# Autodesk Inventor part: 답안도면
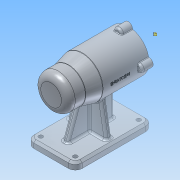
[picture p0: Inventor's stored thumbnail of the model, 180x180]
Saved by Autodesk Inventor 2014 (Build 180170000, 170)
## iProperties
Created: 2019-07
Part Number: 답안도면
Material: 알루미늄 6061
Document SubType Name: Modeling
Designer: net
Density: 2.71 g/cm^3
Appearance: 알루미늄 - 평지
Mass: 644.956 g
Surface Area: 654.406 cm^2
Volume: 237.991 cm^3
Author: net
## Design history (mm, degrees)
sketch "스케치1"
  geometry: L1 (-56, 0)-(56, 0); L2 (-56, 0)-(-50, 0); L3 (-50, 0)-(-50, 10.5); L4 (-50, 10.5)-(-47, 10.5); L5 (-47, 10.5)-(-47, 16); L6 (-47, 16)-(-43, 16); L7 (-43, 16)-(-43, 17.5); L8 (-43, 17.5)-(-25, 17.5); L9 (-25, 17.5)-(-25, 21); L10 (-25, 21)-(-13, 21); L11 (-13, 21)-(-13, 24); L12 (-13, 24)-(41, 24); L13 (41, 24)-(41, 21); L14 (41, 21)-(56, 21); L15 (56, 21)-(56, 30); L16 (56, 30)-(-11, 30); L17 (-31, 25)-(-56, 25); L18 (-56, 25)-(-56, 0); L19 (-31, 25)-(-11, 30); 2 further points
  constraints: 39 end point, 13 parallel, 3 perpendicular, 1 coincident, 1 collinear, 1 horizontal, 1 midpoint
  dimensions: "d0" = 112 distance of L1.start L1.end; "d1" = 42 diameter of L14 L1; "d2" = 60 diameter of L16 L1; "d3" = 50 diameter of L17 L1; "d4" = 48 diameter of L12 L1; "d5" = 42 diameter of L10 L1; "d6" = 35 diameter of L8 L1; "d7" = 32 diameter of L6 L1; "d9" = 21 diameter of L4 L1; "d10" = 15 distance of L13.end L14.end; "d11" = 112 distance between parallel lines of L15 L18; "d12" = 3 distance of L3.end L4.end; "d13" = 4 distance of L5.end L6.end; "d14" = 18 distance of L7.end L8.end; "d15" = 12 distance of L9.end L10.end; "d16" = 54 distance of L11.end L12.end; "d17" = 25 distance from line of L17.start L18; "d18" = 45 distance from line of L18 L16.end
revolve "회전1" sketch "스케치1" stored, may be unused: angle "d19" = 90 deg
fillet "모깎기1" dims "d20" = 10
fillet "모깎기2" dims "d21" = 3
fillet "모깎기3" dims "d22" = 3
fillet "모깎기4" dims "d23" = 0.3
fillet "모깎기5" dims "d24" = 3
node "작업 평면1"
sketch "스케치4"
  geometry: L1 (35, -56)-(-35, -56); L2 (-35, -56)-(-35, 56); L3 (-35, 56)-(35, 56); L4 (35, 56)-(35, -56); L5 (35, -56)-(-35, 56); L6 (-35, -56)-(35, 56); 1 further point
  constraints: 12 end point, 2 midpoint, 2 parallel, 1 horizontal, 1 perpendicular
  dimensions: "d26" = 70 distance of L2.end L3.end; "d27" = 112 distance of L1.end L2.end
extrude "돌출1" join sketch "스케치4" distance "d28" = 10; taper "d29" = 0 deg
fillet "모깎기6" dims "d30" = 10
sketch "스케치5"
  geometry: C1 r 3 at (-25, 46); C2 r 3 at (25, 46); C3 r 3 at (25, -46); C4 r 3 at (-25, -46); A1 r 7 centre (25, 46) between (32, 46) and (25, 53) reference; A2 r 7 centre (-25, 46) between (-25, 53) and (-32, 46) reference; A3 r 7 centre (-25, -46) between (-32, -46) and (-25, -53) reference; A4 r 7 centre (25, -46) between (25, -53) and (32, -46) reference; 1 further point
  constraints: 4 centre point, 4 coincident
  dimensions: "d32" = 6 diameter of C1; "d33" = 6 diameter of C2; "d34" = 6 diameter of C3; "d35" = 6 diameter of C4
extrude "돌출2" cut sketch "스케치5" distance "d36" = 10; taper "d37" = 0 deg
sketch "스케치6"
  geometry: L1 (-28, 4)-(28, 4); L2 (28, 4)-(28, -4); L3 (28, -4)-(-28, -4); L4 (-28, -4)-(-28, 4); L5 (-28, 4)-(28, -4); L6 (28, 4)-(-28, -4); L7 (-25, -56)-(25, -56) reference; L8 (25, 56)-(-25, 56) reference; L9 (6.365, -43.821)-(-6.365, -43.821); L10 (-4, 31)-(-4, -36); L11 (-4, -36)-(4, -36); L12 (4, -36)-(4, 31); L13 (4, 31)-(-4, 31); 3 further points
  constraints: 22 end point, 5 parallel, 4 midpoint, 2 perpendicular, 1 horizontal, 1 vertical alignment
  dimensions: "d46" = 8 distance between parallel lines of L3 L1; "d47" = 56 distance between parallel lines of L4 L2; "d87" = 25 distance between parallel lines of L8 L13; "d88" = 20 distance between parallel lines of L7 L11; "d90" = 8 distance of L12.end L10.start
extrude "돌출3" join sketch "스케치6" stored distance "d54" = 10; taper "d55" = 0 deg
feature "면 기울기1" dims angle "d56" = 20 deg
feature "면 기울기2" dims angle "d57" = 10 deg
chamfer "모따기1" distance "d58" = 3; stored, may be unused: second distance "d59" = 2, angle "d60" = 45 deg
chamfer "모따기2" distance "d63" = 1; stored, may be unused: second distance "d64" = 2, angle "d65" = 45 deg
sketch "스케치7"
  geometry: C1 r 6 at (0, -30); 1 further point
  constraints: 2 vertical alignment, 1 centre point, 1 other
  dimensions: "d66" = 12 diameter of C1
extrude "돌출4" join sketch "스케치7" distance "d67" = 16; taper "d68" = 0 deg
sketch "스케치8"
  geometry: A1 r 6 centre (0, 0) between (-5.97, 0.6) and (5.97, 0.6) reference; 1 further point
  constraints: 1 coincident
hole "구멍1" sketch "스케치8" at (0, 0) diameter "d69" = 3.242; stored, may be unused: countersink angle "d73" = 90 deg, drill point angle "d75" = 118 deg; dims "d70" = 8, "d71" = 4, "d72" = 2, "d74" = 11
fillet "모깎기10" dims "d79" = 3
fillet "모깎기11" dims "d80" = 1
node "작업 평면2"
sketch "스케치9"
  geometry: L1 (56, 6.771)-(56, 29.226) reference; 2 further points
  constraints: 1 other
  dimensions: "d82" = 42 distance from line of L1 point (14, -0.137)
feature "엠보싱1" sketch "스케치9" dims "d83" = 0.5, "d84" = 0
feature "면 기울기3" dims angle "d91" = 20 deg
fillet "모깎기12" dims "d92" = 3
fillet "모깎기13" dims "d93" = 3
fillet "모깎기14" dims "d94" = 3
node "솔리드1"
pattern_circular "원형 패턴1" dims angle "d77" = 360 deg
